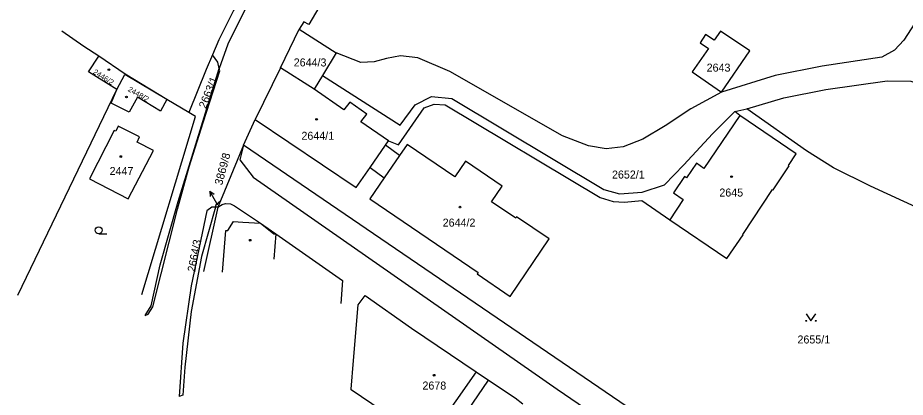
# Model space of a CAD drawing. Extents: x -527335 to -526256, y -1079142 to -1077809.
# Drawn here: x -527320.7 to -527132.2, y -1078726.1 to -1078645.5 of the extents above; entities that cross this region are included whole.
import ezdxf

# ---------------------------------------------------------------- set-up
doc = ezdxf.new("R2010")
doc.units = 0
for name, color, linetype in [('Vrstva 1', 7, 'Continuous'), ('Vrstva 2', 7, 'Continuous'), ('Vrstva 3', 7, 'Continuous'), ('Vrstva 4', 7, 'Continuous'), ('Vrstva 5', 7, 'Continuous'), ('Vrstva 7', 7, 'Continuous')]:
    doc.layers.add(name, color=color, linetype=linetype)

msp = doc.modelspace()

# ---------------------------------------------------------------- linework, layer by layer
at = {"layer": 'Vrstva 1'}
for p, q in [((-527264.89, -1078656.14), (-527260.95, -1078647.97)), ((-527260.95, -1078647.97), (-527253.05, -1078652.95)), ((-527297.89, -1078657.48), (-527303.49, -1078653.69)), ((-527264.89, -1078656.14), (-527270.24, -1078667.1)), ((-527257.71, -1078660.67), (-527264.89, -1078656.14)), ((-527289.01, -1078662.86), (-527297.89, -1078657.48)), ((-527320.71, -1078704.47), (-527299.68, -1078660.79)), ((-527284.39, -1078665.65), (-527289.01, -1078662.86)), ((-527272.74, -1078672.59), (-527270.24, -1078667.1)), ((-527245.87, -1078677.33), (-527242.58, -1078672.56)), ((-527242.58, -1078672.56), (-527241.95, -1078671.65)), ((-527272.74, -1078672.59), (-527277.63, -1078684.38)), ((-527277.63, -1078684.38), (-527278.21, -1078685.77)), ((-527278.21, -1078685.77), (-527281.21, -1078699.45)), ((-527278.21, -1078685.77), (-527278.72, -1078685.77)), ((-527233.34, -1078735.68), (-527249.9, -1078724.58))]:
    msp.add_line(p, q, dxfattribs=at)
for points in [[(-527247.54, -1078602.12), (-527247.04, -1078603.09), (-527247.06, -1078604.56), (-527247.44, -1078605.48), (-527258.5, -1078620.92), (-527264.64, -1078630.06), (-527269.21, -1078637.79), (-527272.96, -1078644.85), (-527276.06, -1078651.14), (-527277.91, -1078656.32)], [(-527259.82, -1078619.66), (-527262.34, -1078623.21), (-527266.21, -1078628.65), (-527267.92, -1078631.37), (-527269.54, -1078634.12), (-527274.93, -1078644.11), (-527277.98, -1078650.21), (-527279.35, -1078653.36)], [(-527116.37, -1078625.34), (-527132.46, -1078650.27), (-527134.42, -1078652.38), (-527137.13, -1078653.92), (-527149.78, -1078655.77), (-527159.8, -1078657.78), (-527171.17, -1078661.31), (-527177.71, -1078664.84), (-527183.15, -1078668.47), (-527187.88, -1078671.32), (-527192.11, -1078672.93), (-527195.71, -1078673.39), (-527199.46, -1078672.73), (-527204.98, -1078670.57), (-527228.94, -1078656.95), (-527235.73, -1078654.01), (-527239.42, -1078653.58), (-527242.39, -1078654.19), (-527245.02, -1078654.86), (-527247.81, -1078654.99), (-527253.05, -1078652.95)], [(-527254.01, -1078637.26), (-527253.42, -1078637.6), (-527258.88, -1078646.96), (-527259.9, -1078646.35), (-527260.95, -1078647.97)], [(-527303.49, -1078653.69), (-527306.7, -1078651.62), (-527311.35, -1078648.37)], [(-527172.75, -1078650.31), (-527174.56, -1078649.06), (-527175.72, -1078650.82), (-527173.95, -1078652.04), (-527177.39, -1078657.02), (-527171.17, -1078661.31), (-527165.16, -1078652.51), (-527171.39, -1078648.34), (-527172.75, -1078650.31)], [(-527299.68, -1078660.79), (-527305.69, -1078656.98), (-527303.49, -1078653.69)], [(-527279.35, -1078653.36), (-527280.71, -1078656.51), (-527284.39, -1078665.65)], [(-527277.91, -1078656.32), (-527278.23, -1078654.96), (-527279.35, -1078653.36)], [(-527253.05, -1078652.95), (-527255.96, -1078657.77), (-527257.71, -1078660.67)], [(-527293.64, -1078708.79), (-527292.39, -1078706.75), (-527290.45, -1078697.98), (-527286.64, -1078684.53), (-527277.91, -1078656.32)], [(-527293.64, -1078708.79), (-527292.98, -1078708.5), (-527292.02, -1078706.97), (-527286.76, -1078686.2), (-527284.3, -1078677.2), (-527281.35, -1078667.78), (-527277.8, -1078656.81), (-527277.91, -1078656.32)], [(-527299.68, -1078660.79), (-527297.95, -1078657.59), (-527297.89, -1078657.48)], [(-527165.78, -1078664.86), (-527157.95, -1078662.5), (-527148.99, -1078660.76), (-527136.01, -1078658.93), (-527130.99, -1078659.02), (-527128.08, -1078659.99)], [(-527289.01, -1078662.86), (-527290.41, -1078665.38), (-527295.27, -1078662.42), (-527297.02, -1078665.61), (-527300.83, -1078663.65), (-527299.68, -1078660.79)], [(-527241.95, -1078671.65), (-527247.8, -1078667.64), (-527246.57, -1078665.99), (-527250.13, -1078663.43), (-527251.4, -1078665.05), (-527257.71, -1078660.67)], [(-527241.95, -1078671.65), (-527239.8, -1078672.53), (-527234.35, -1078664.64), (-527232.21, -1078663.91), (-527229.87, -1078664), (-527196.99, -1078683.7), (-527194.2, -1078684.54), (-527191.82, -1078684.7), (-527188.1, -1078684.36), (-527182.19, -1078688.47)], [(-527167.32, -1078666.31), (-527168.39, -1078665.42), (-527165.78, -1078664.86)], [(-527111.05, -1078694.45), (-527119.22, -1078690.63), (-527139.54, -1078681.28), (-527147.37, -1078677.43), (-527153.14, -1078673.82), (-527165.78, -1078664.86)], [(-527294.36, -1078704.33), (-527282.97, -1078666.51), (-527284.39, -1078665.65)], [(-527167.32, -1078666.31), (-527174.91, -1078677.52), (-527176.52, -1078676.39), (-527178.62, -1078679.53), (-527179.03, -1078679.24), (-527181.37, -1078682.74), (-527179.31, -1078684.13), (-527182.19, -1078688.47)], [(-527182.19, -1078688.47), (-527170.06, -1078696.66), (-527166.56, -1078691.66), (-527166.69, -1078691.58), (-527160.32, -1078682), (-527160.2, -1078682.08), (-527156.82, -1078677), (-527156.95, -1078676.91), (-527155.3, -1078674.43), (-527167.32, -1078666.31)], [(-527291.89, -1078673.73), (-527295.37, -1078671.93), (-527294.81, -1078670.79), (-527299.34, -1078668.53), (-527299.9, -1078669.59), (-527300.19, -1078669.44), (-527305.45, -1078679.75), (-527297.22, -1078683.96), (-527291.89, -1078673.73)], [(-527270.24, -1078667.1), (-527248.82, -1078681.6), (-527245.87, -1078677.33)], [(-527245.87, -1078677.33), (-527242.86, -1078679.54), (-527245.9, -1078684), (-527222.92, -1078699.66), (-527223.12, -1078699.95), (-527216.12, -1078704.72), (-527207.8, -1078692.52), (-527214.72, -1078687.81), (-527214.92, -1078688.1), (-527220.08, -1078684.6), (-527217.82, -1078681.28), (-527225.58, -1078676), (-527227.84, -1078679.32), (-527238, -1078672.41), (-527239.62, -1078674.79), (-527242.58, -1078672.56)], [(-527148.09, -1078757.41), (-527188.11, -1078730.34), (-527272.74, -1078672.59)], [(-527278.72, -1078685.77), (-527279.49, -1078685.76), (-527280.57, -1078686.57), (-527283.88, -1078702.5), (-527285.64, -1078714.62), (-527286.43, -1078726)], [(-527278.72, -1078685.77), (-527278.54, -1078685.21), (-527277.63, -1078684.38)], [(-527278.21, -1078685.77), (-527277.29, -1078685.19), (-527276.55, -1078684.95), (-527275.53, -1078685.03), (-527274.64, -1078685.46), (-527269.13, -1078689.18), (-527265.85, -1078691.43), (-527251.69, -1078701.32), (-527252.04, -1078706.2)], [(-527278.72, -1078685.77), (-527281.7, -1078696.22), (-527283.84, -1078707.91), (-527285.21, -1078719.78), (-527285.64, -1078725.69), (-527286.43, -1078726)], [(-527249.9, -1078724.58), (-527249.9, -1078724.42), (-527249.39, -1078718.37), (-527248.39, -1078706.48), (-527246.91, -1078704.54), (-527237.07, -1078711.48), (-527223.28, -1078720.72)], [(-527223.28, -1078720.72), (-527231.93, -1078733.05), (-527233.34, -1078735.68)], [(-527223.28, -1078720.72), (-527220.7, -1078722.5), (-527215.01, -1078726.29), (-527213.43, -1078727.51)]]:
    msp.add_lwpolyline(points, dxfattribs=at)
at = {"layer": 'Vrstva 3'}
msp.add_line((-527303.51, -1078691.42), (-527301.76, -1078691.42), dxfattribs=at)
msp.add_lwpolyline([(-527153.18, -1078708.41), (-527152.18, -1078709.91), (-527151.18, -1078708.41)], dxfattribs=at)
for centre, radius in [((-527303.51, -1078690.67), 0.75), ((-527153.18, -1078709.91), 0.1), ((-527151.18, -1078709.91), 0.1)]:
    msp.add_circle(centre, radius, dxfattribs=at)
at = {"layer": 'Vrstva 4'}
for p, q in [((-527289.01, -1078662.86), (-527297.95, -1078657.59)), ((-527255.96, -1078657.77), (-527239.47, -1078668.37)), ((-527236.26, -1078664.04), (-527232.83, -1078662.22)), ((-527232.83, -1078662.22), (-527228.51, -1078662.65)), ((-527228.51, -1078662.65), (-527196.21, -1078682)), ((-527239.47, -1078668.37), (-527236.26, -1078664.04)), ((-527173.08, -1078670.19), (-527168.39, -1078665.42)), ((-527179.19, -1078676.8), (-527173.08, -1078670.19)), ((-527272.74, -1078672.59), (-527273.5, -1078675.7)), ((-527273.5, -1078675.7), (-527270.71, -1078679.37)), ((-527239.62, -1078674.79), (-527242.86, -1078679.54)), ((-527183.33, -1078681), (-527179.19, -1078676.8)), ((-527270.71, -1078679.37), (-527206.11, -1078724.43)), ((-527188.07, -1078682.57), (-527183.33, -1078681)), ((-527196.21, -1078682), (-527192.87, -1078682.95)), ((-527192.87, -1078682.95), (-527188.07, -1078682.57)), ((-527276.08, -1078690.72), (-527274.86, -1078688.78)), ((-527274.86, -1078688.78), (-527272.89, -1078688.92)), ((-527272.89, -1078688.92), (-527269.13, -1078689.18)), ((-527269.13, -1078689.18), (-527266.31, -1078691.4)), ((-527277.18, -1078699.56), (-527276.49, -1078690.69)), ((-527276.49, -1078690.69), (-527276.08, -1078690.72)), ((-527266.31, -1078691.4), (-527265.85, -1078691.43)), ((-527265.85, -1078691.43), (-527266.27, -1078696.79)), ((-527274.8, -1078801.86), (-527220.7, -1078722.5)), ((-527206.11, -1078724.43), (-527130.49, -1078775.7))]:
    msp.add_line(p, q, dxfattribs=at)
at = {"layer": 'Vrstva 5'}
for centre in [(-527301.35, -1078656.53), (-527297.61, -1078662.35), (-527257.22, -1078667.1), (-527298.81, -1078675), (-527169.06, -1078679.28), (-527226.75, -1078685.75), (-527271.33, -1078692.78), (-527232.25, -1078721.46)]:
    msp.add_circle(centre, 0.175, dxfattribs=at)
at = {"layer": 'Vrstva 7'}
for p, q in [((-527278.44, -1078685), (-527279.9, -1078682.38)), ((-527279.9, -1078682.38), (-527278.97, -1078683.01)), ((-527279.9, -1078682.38), (-527279.85, -1078683.49)), ((-527278.26, -1078685.32), (-527278.44, -1078685))]:
    msp.add_line(p, q, dxfattribs=at)

# ---------------------------------------------------------------- texts
at = {"layer": 'Vrstva 2'}
for s, p in [('2644/3', (-527262.08, -1078655.86)), ('2643', (-527174.35, -1078656.96)), ('2644/1', (-527260.44, -1078671.44)), ('2447', (-527301.2, -1078678.93)), ('2652/1', (-527194.46, -1078679.68)), ('2645', (-527171.65, -1078683.5)), ('2644/2', (-527230.43, -1078689.89)), ('2655/1', (-527155.05, -1078714.72)), ('2678', (-527234.73, -1078724.51))]:
    msp.add_text(s, height=1.7, dxfattribs=at).set_placement(p)
for s, height, rotation, p in [('2446/2', 1.14, 328, (-527304.82, -1078657.32)), ('2663/1', 1.7, 68, (-527280.76, -1078664.93)), ('2448/2', 1.139, 330, (-527297.43, -1078661.03)), ('3869/8', 1.7, 75, (-527277.3, -1078681.21)), ('2664/3', 1.7, 79, (-527283.03, -1078699.65))]:
    msp.add_text(s, height=height, rotation=rotation, dxfattribs=at).set_placement(p)

doc.saveas('drawing.dxf')
